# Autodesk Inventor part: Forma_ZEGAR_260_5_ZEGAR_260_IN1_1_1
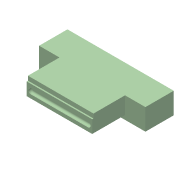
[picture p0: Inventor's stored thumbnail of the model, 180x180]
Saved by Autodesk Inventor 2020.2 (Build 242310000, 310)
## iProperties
Created: 2015-01
Part Number: Forma_ZEGAR_260_5_ZEGAR_260_IN1_1_1
Material: Ogólny
Document SubType Name: Modeling
Designer: F.Stasiak
Density: 1 g/cm^3
Appearance: Domyślna
Catalog Web Link: www.expertbooks.pl
Manager: www.cadconsulting.pl
Company: Fabian Stasiak CAD Consulting
Author: F.Stasiak
Subject: Zbiór ćwiczeń. Autodesk Inventor 2020. Kurs Professional
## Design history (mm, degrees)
node "Forma_ZEGAR_260_4_ZEGAR_260_IN1_Base"
feature "Bryła1::Forma_ZEGAR_260_4_ZEGAR_260_IN1_Base"
tag "Bryła wyprowadzona1"
node "Bryła1"
feature "Forma_ZEGAR_260_4_ZEGAR_260_IN1_Base_Bodies"
